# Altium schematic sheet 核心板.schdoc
size 297 x 209 mm; Symbol: Drawing-Symbol_A4; Company: 嘉立创EDA; Version: V1.0; Page Size: A4; @Project Name: 水墨屏demo1; @Page Count: 1; @Update Date: 2026-02-28; @Create Date: 2026-02-28; @Schematic Name: Schematic1; @Page No: 1; @Page Name: P1; Device: Drawing-Symbol_A4; @Board Name: 2_STM32F407最小系统; @Create Time: 14:39:36; @Update Time: 14:39:36; @Assembly Variant: Basic; Border: 1; Title Block Position: 3; Size: A4; Width: 1170; Height: 825; Region Start: 1; X Region Count: 6; Y Region Count: 4; Blade Width: 10
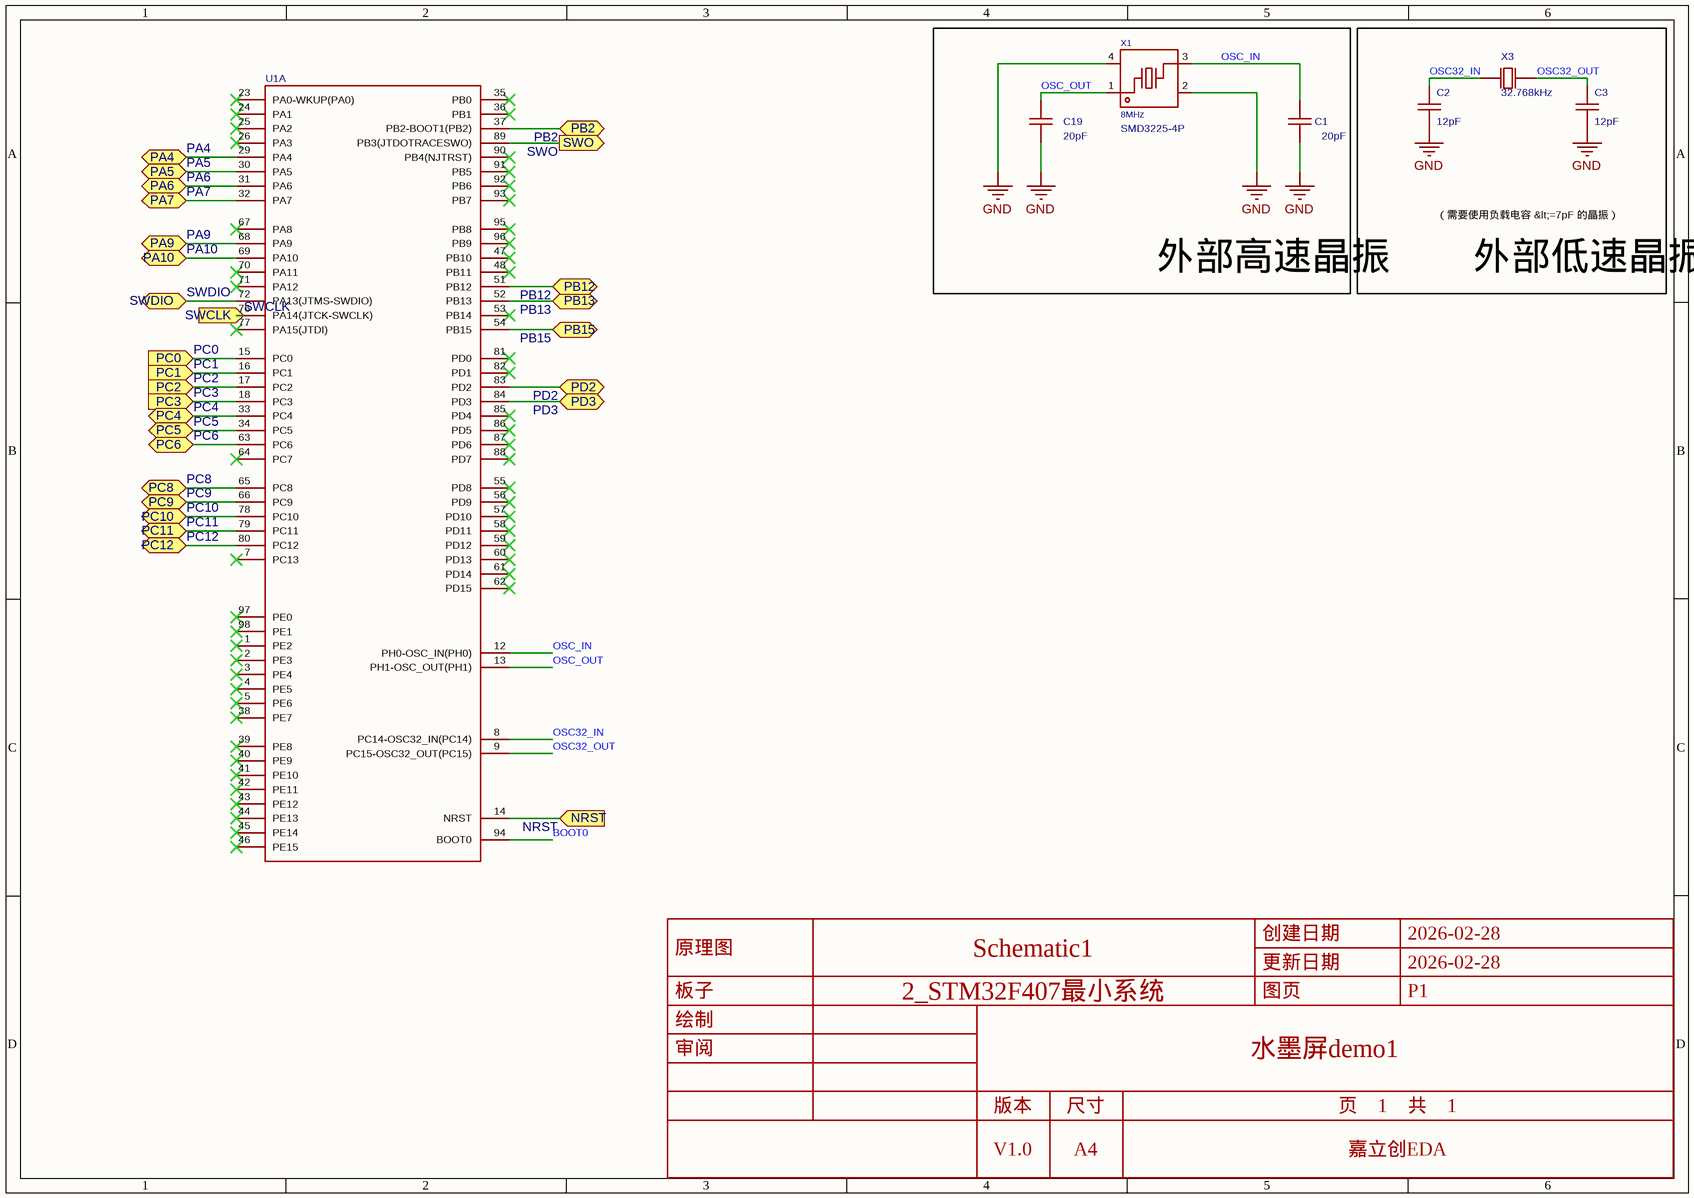
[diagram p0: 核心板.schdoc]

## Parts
C1  20pF  [C0603]
C2  12pF  [C0603]
C3  12pF  [C0603]
C19  20pF  [C0603]
U1  (no value)  [LQFP-100_L14.0-W14.0-P0.50-LS16.0-BL]  (part A of 2)
X1  Supplier Footprint: SMD3225-4P  [CRYSTAL-SMD_4P-L3.2-W2.5-BL]  (hidden comment: 8MHz)
X3  32.768kHz  [OSC-SMD_2P-L3.2-W1.5]

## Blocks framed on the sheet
外部高速晶振: C1 C19 X1
外部低速晶振: C2 C3 X3

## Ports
NRST (in), PA4 (bidir), PA5 (bidir), PA6 (bidir), PA7 (bidir), PA9 (bidir), PA10 (bidir), PB2 (bidir), PB12 (bidir), PB13 (bidir), PB15 (bidir), PC0 (in), PC1 (in), PC2 (in), PC3 (in), PC4 (bidir), PC5 (bidir), PC6 (bidir), PC8 (bidir), PC9 (bidir), PC10 (bidir), PC11 (bidir), PC12 (bidir), PD2 (bidir), PD3 (bidir), SWCLK (in), SWDIO (bidir), SWO (out)

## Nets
GND: C1.1 C2.1 C3.1 C19.1 X1.2(GND) X1.4(GND)
BOOT0: U1.94(BOOT0)
NRST: U1.14(NRST) ; port NRST
OSC32_IN: C2.2 U1.8(PC14-OSC32_IN(PC14)) X3.1(OSC1)
OSC32_OUT: C3.2 U1.9(PC15-OSC32_OUT(PC15)) X3.2(OSC2)
OSC_IN: C1.2 U1.12(PH0-OSC_IN(PH0)) X1.3
OSC_OUT: C19.2 U1.13(PH1-OSC_OUT(PH1)) X1.1
PA4: U1.29(PA4) ; port PA4
PA5: U1.30(PA5) ; port PA5
PA6: U1.31(PA6) ; port PA6
PA7: U1.32(PA7) ; port PA7
PA9: U1.68(PA9) ; port PA9
PA10: U1.69(PA10) ; port PA10
PB2: U1.37(PB2-BOOT1(PB2)) ; port PB2
PB12: U1.51(PB12) ; port PB12
PB13: U1.52(PB13) ; port PB13
PB15: U1.54(PB15) ; port PB15
PC0: U1.15(PC0) ; port PC0
PC1: U1.16(PC1) ; port PC1
PC2: U1.17(PC2) ; port PC2
PC3: U1.18(PC3) ; port PC3
PC4: U1.33(PC4) ; port PC4
PC5: U1.34(PC5) ; port PC5
PC6: U1.63(PC6) ; port PC6
PC8: U1.65(PC8) ; port PC8
PC9: U1.66(PC9) ; port PC9
PC10: U1.78(PC10) ; port PC10
PC11: U1.79(PC11) ; port PC11
PC12: U1.80(PC12) ; port PC12
PD2: U1.83(PD2) ; port PD2
PD3: U1.84(PD3) ; port PD3
SWCLK: U1.76(PA14(JTCK-SWCLK)) ; port SWCLK
SWDIO: U1.72(PA13(JTMS-SWDIO)) ; port SWDIO
SWO: U1.89(PB3(JTDOTRACESWO)) ; port SWO

Not connected (* = marked no-connect by the designer): U1 1(PE2)* 2(PE3)* 3(PE4)* 4(PE5)* 5(PE6)* 7(PC13)* 23(PA0-WKUP(PA0))* 24(PA1)* 25(PA2)* 26(PA3)* 35(PB0)* 36(PB1)* 38(PE7)* 39(PE8)* 40(PE9)* 41(PE10)* 42(PE11)* 43(PE12)* 44(PE13)* 45(PE14)* 46(PE15)* 47(PB10)* 48(PB11)* 53(PB14)* 55(PD8)* 56(PD9)* 57(PD10)* 58(PD11)* 59(PD12)* 60(PD13)* 61(PD14)* 62(PD15)* 64(PC7)* 67(PA8)* 70(PA11)* 71(PA12)* 77(PA15(JTDI))* 81(PD0)* 82(PD1)* 85(PD4)* 86(PD5)* 87(PD6)* 88(PD7)* 90(PB4(NJTRST))* 91(PB5)* 92(PB6)* 93(PB7)* 95(PB8)* 96(PB9)* 97(PE0)* 98(PE1)*

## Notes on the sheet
- （需要使用负载电容 &lt;=7pF 的晶振）

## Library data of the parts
C1 C19 = CL10C200JB8NNNC: 容值:20pF;精度:±5%;额定电压:50V;温度系数:C0G;; Manufacturer: SAMSUNG(三星); AddInBom: yes; ModelId: ac125912035d415993ca9572d50418b10819f05c4eef4c71ace90d822a990e87; ModelName: C0603_L1.6-W0.8-H0.8; ModelTransform: 62.992,31.496,0,0,0,0,0,0,0; Tolerance: ±5%; Voltage Rating: 50V; Temperature Coefficient: C0G
C2 C3 = CL10C120JB8NNNC: 容值:12pF;精度:±5%;额定电压:50V;温度系数:C0G;; Manufacturer: SAMSUNG(三星); AddInBom: yes; ModelId: ac125912035d415993ca9572d50418b10819f05c4eef4c71ace90d822a990e87; ModelName: C0603_L1.6-W0.8-H0.8; ModelTransform: 62.992,31.496,0,0,0,0,0,0,0; Tolerance: ±5%; Voltage Rating: 50V; Temperature Coefficient: C0G
U1 = STM32F407VET6【自修改】: CPU内核:ARM Cortex-M4;CPU最大主频:168MHz;工作电压范围:1.8V~3.6V;内部振荡器:有;程序 FLASH容量:512K@x8bit;RAM总容量:192KB;EEPROM/数据 FLASH容量:-;GPIO端口数量:82;ADC(单元数/通道数/位数):1@x16ch/12bit;DAC(单元数/通道数/位数):1@x2ch/12bit;外设/功能/协议栈:欠压检测/复位；DMA；LCD驱动；看门狗；POR；PWM;工作温度范围:-40℃~+85℃;; Manufacturer: ST(意法半导体); Relevance: []; Maximum Frequency: 168MHz; Internal Oscillator: 有; RAM Size: 192KB; GPIO Ports Number: 82; 3D Model: 469e6cc70557486dbd01fd12ff814964; 3D Model Transform: 629.92,629.92,0,0,0,0,0,0,0; AddInBom: yes; ModelName: LQFP-100_L14.0-W14.0-H1.4-LS16.0-P0.50
X1 = X32258MOB4SI: 频率:8MHz;频率公差:±10ppm;负载电容:12pF;; Manufacturer: YXC(扬兴晶振); 3D Model: ae22b8d143894765bc8100c37cb6356f; 3D Model Transform: 125.984,98.425,0,0,0,0,0,0,0; Crystal Type: 贴片无源晶振; Frequency Stability: ±30ppm; Load Capacitance: 12pF; Equivalent Series Resistance (ESR): 150Ω; AddInBom: yes; ModelName: OSC-SMD_4P-L3.2-W2.5-H1.0; Normal temperature Frequency Tolerance: ±10ppm
X3 = XKXEL89CJI-SUAYLC-32.768K: 晶振类型:贴片晶振;频率:32.768kHz;常温频差:±20ppm;负载电容:7pF;频率稳定度:±30ppm;; Manufacturer: YXC(扬兴晶振); AddInBom: yes; ModelId: 8fc48a4f9b8d4391a4331ccdd90d2df10819f05c4eef4c71ace90d822a990e87; ModelName: OSC-SMD_2P-L3.2-W1.5-H0.9; ModelTransform: 125.984,59.055,0,0,0,0,0,0,0; Normal temperature Frequency Tolerance: ±20ppm; Load Capacitance: 7pF; Frequency Stability: ±30ppm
